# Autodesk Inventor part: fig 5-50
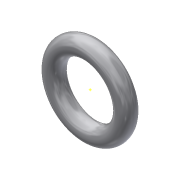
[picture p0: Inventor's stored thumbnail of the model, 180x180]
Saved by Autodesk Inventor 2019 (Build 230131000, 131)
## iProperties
Created: 2010-02
Part Number: fig 5-50
Document SubType Name: Modeling
Designer: CADSoft
Density: 1 g/cm^3
Material: Generic
Appearance: Default
Author: CADSoft
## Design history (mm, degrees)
sketch "Sketch1"
  geometry: L1 (0, 21.37)-(0, -16.247); C1 r 5 at (20.026, 0); 1 further point
  constraints: 2 end point, 1 centre point
  dimensions: "d0" = 10 diameter of C1
revolve "Revolution1" sketch "Sketch1" stored, may be unused: angle "d1" = 90 deg
workpoint "Work Point1"
body "Solid1"
